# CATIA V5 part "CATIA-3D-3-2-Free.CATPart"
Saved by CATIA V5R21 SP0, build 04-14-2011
Part number: CATIA-3D-3-2-Free
Bounding box of the stored display mesh (mm): x -80 to 20, y -20 to 20, z -35 to 20
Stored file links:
  C:\Users\Rasoul Mohammadi\Desktop\CATIA-Free\3D\CATIA-3D-3-2-Free.CATPart
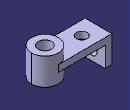
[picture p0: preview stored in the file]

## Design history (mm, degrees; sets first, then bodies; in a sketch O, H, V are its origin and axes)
Body1 (main body)
  Sketch1 on zx-plane, origin (0, 0, 0), H (-1, 0, 0), V (0, 0, 1)
    point P1 (0, -5)
    line L1 (0, -5) -> (0, 5)
    line L2 (0, 5) -> (80, 5)
    line L3 (80, 5) -> (80, -35)
    line L4 (80, -35) -> (70, -35)
    line L5 (70, -35) -> (70, -5)
    line L6 (70, -5) -> (0, -5)
    length L3 = 40
    length L1 = 10
    length L4 = 10
    distance L3 V = 80
    coincidence: P1 V
    vertical: L1 V, L3 V, L5 V
    horizontal: L2 H, L4 H, L6 H
    symmetry: L2 L6 H
  Pad1: profile Sketch1, direction (0, 1, 0), length 20, mirrored extent
  Sketch2 on xy-plane, origin (0, 0, 0), H (1, 0, 0), V (0, 1, 0)
    circle A1 centre (0, 0) radius 20
    radius A1 = 20
  Pad2: profile Sketch2, direction (0, 0, 1), length 20, mirrored extent
  Sketch3 on end face of Pad2, origin (3.812, 1.5944, 20), H (1, 0, 0), V (0, 1, 0)
    point P1 (-3.812, -1.5944)
    reference projected circle E1 centre (-3.812, -1.5944) radius 20 from edge [face of Pad2 from Sketch2.A1 | end face of Pad2]
    concentricity: E1 P1
  Hole1: placed by Sketch3, at (0, 0, 20) direction (0, 0, -1), diameter 20, through (limit type 6)
  Sketch4 on face of Pad1 from Sketch1.L2, origin (-52.2585, 2.2965, 5), H (1, 0, 0), V (0, 1, 0)
    point P1 (-2.7415, -2.2965)
    reference intersected line E1 through (0, -2.2965) direction (-1, 0) from zx-plane
    reference projected line E2 (-27.7415, -22.2965) -> (-27.7415, 17.7035) from edge [face of Pad1 from Sketch1.L2 | face of Pad1 from Sketch1.L3]
    distance P1 E2 = 25
    coincidence: P1 E1
  Hole2: placed by Sketch4, at (-55, 0, 5) direction (0, 0, -1), diameter 16, through (limit type 6)
  Sketch5 on face of Pad1 from Sketch1.L5, origin (-70, 7.1981, -25.3986), H (0, 1, 0), V (0, 0, 1)
    point P1 (-7.1981, 5.3986)
    reference intersected line E1 through (-7.1981, 0) direction (0, 1) from zx-plane
    reference projected line E2 (-27.1981, -9.6014) -> (12.8019, -9.6014) from edge [face of Pad1 from Sketch1.L4 | face of Pad1 from Sketch1.L5]
    distance E2 P1 = 15
    coincidence: P1 E1
  Hole3: placed by Sketch5, at (-70, 0, -20) direction (-1, 0, 0), diameter 16, through (limit type 6)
